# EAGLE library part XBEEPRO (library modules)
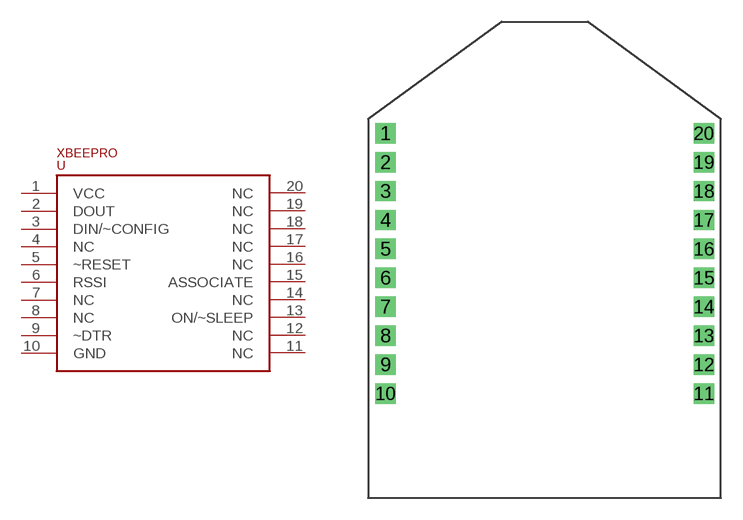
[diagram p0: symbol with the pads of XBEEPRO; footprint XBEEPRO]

Designator prefix U

## XBEEPRO  [XBEEPRO]
1  VCC
2  DOUT
3  DIN/~CONFIG
4  NC
5  ~RESET
6  RSSI
7  NC
8  NC
9  ~DTR
10  GND
11  NC
12  NC
13  ON/~SLEEP
14  NC
15  ASSOCIATE
16  NC
17  NC
18  NC
19  NC
20  NC

## Footprint XBEEPRO (pad centres in mm)
drill 0.9 square: 1 0,0; 2 0,-2; 3 0,-4; 4 0,-6; 5 0,-8; 6 0,-10; 7 0,-12; 8 0,-14; 9 0,-16; 10 0,-18; 11 22,-18; 12 22,-16; 13 22,-14; 14 22,-12; 15 22,-10; 16 22,-8; 17 22,-6; 18 22,-4; 19 22,-2; 20 22,0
